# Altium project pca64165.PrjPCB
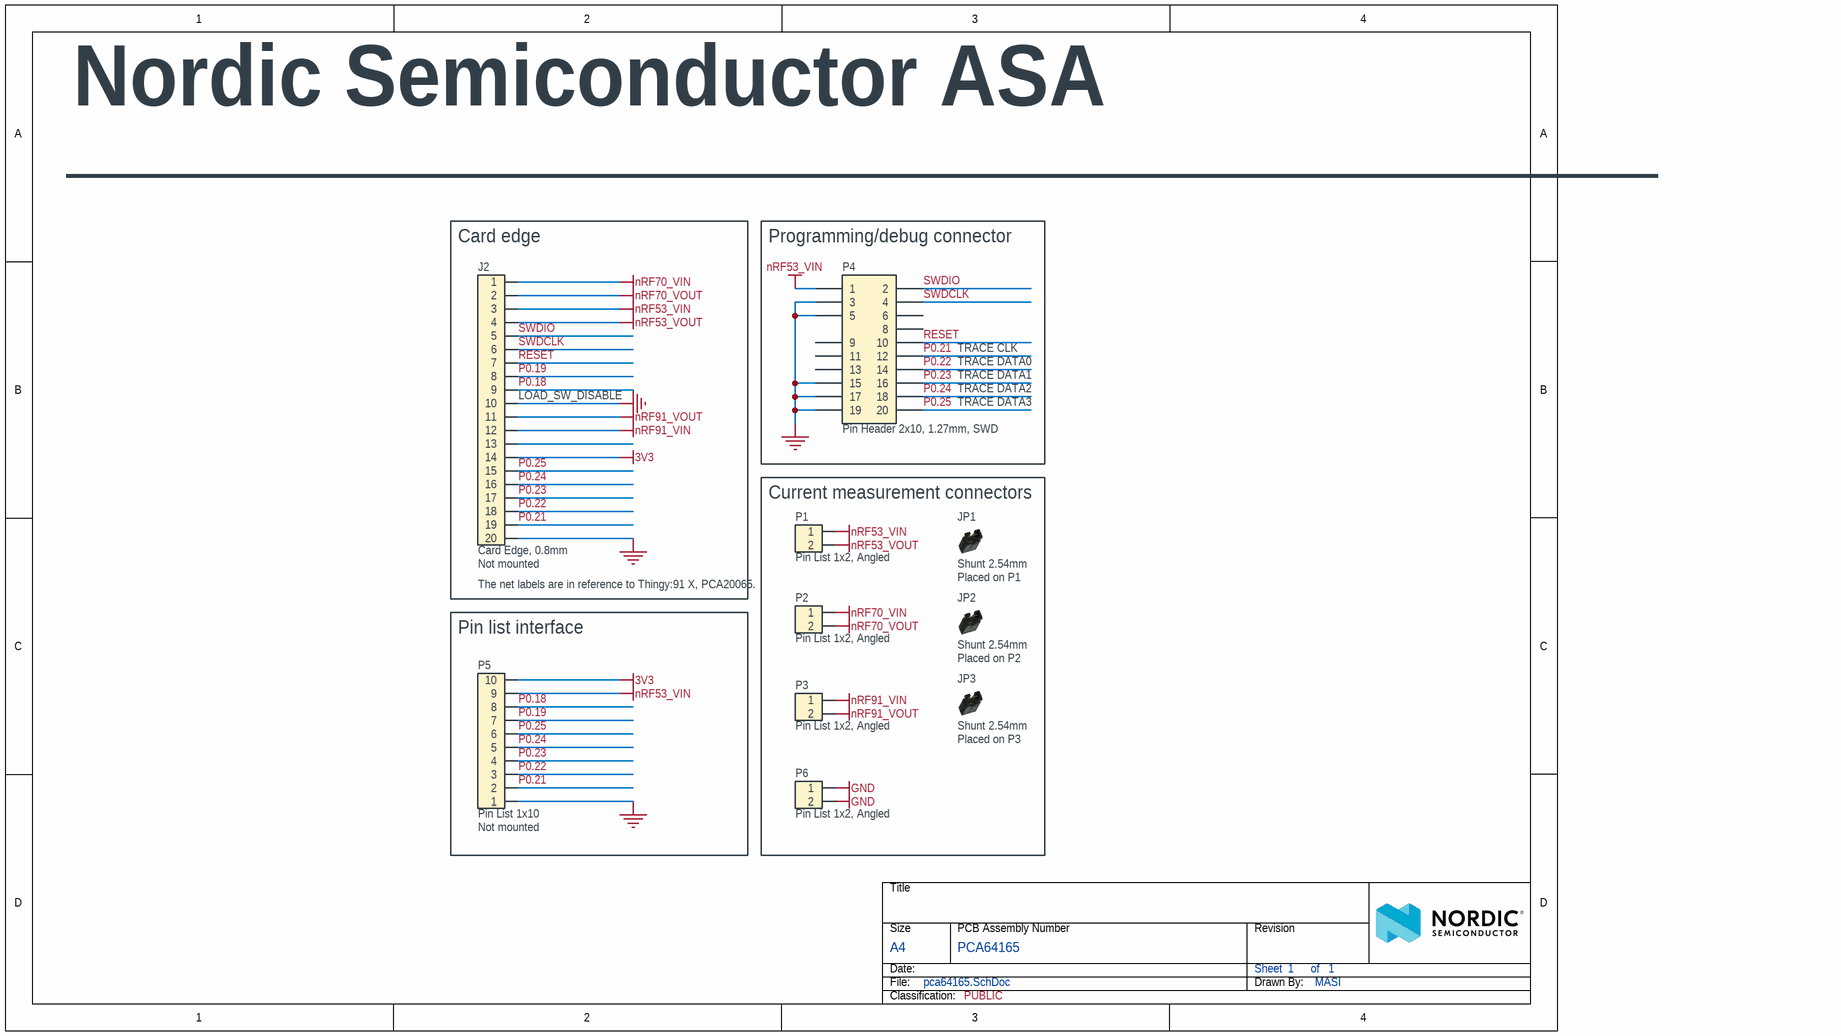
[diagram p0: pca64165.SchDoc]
Author: HANY/MASI; BoardThickness: 1.0mm; BoardTitle: Thingy:91 X Current Measurement and Debug Board; Classification: PUBLIC; Compliance: RoHS, REACH, Halogen-Free; Designer: HANY/MASI; Dielectric: FR-4 Halogen-Free IPC-4101/92; NrOfLayers: 2; Organization: Nordic Semiconductor; PCAName: PCA64165; PCARevision: 1.1.0; PCBNumber: 400763; PCBRevision: 0064HANY; PCBStackup: 2021.240176; ProductName: Thingy:91 X Current Measurement and Debug Board; ProjectName: Thingy:91 X; ProjectNumber: 4492; SilkscreenColor: White, Halogen Free; SoldermaskColor: Blue, Halogen Free; SurfaceFinish: ENIG Gold
1 sheet, 10 parts. Net scope: global (net labels, ports and power ports of the same name join across sheets).
Board file: 400763.PcbDoc

## Sheet pca64165.SchDoc: =BoardTitle
size A4; Organization: Nordic Semiconductor; Revision: 1.1.0; SheetNumber: 1; SheetTotal: 1; Author: HANY/MASI; CompanyName: Nordic Semiconductor; DrawnBy: MASI

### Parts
J2  Card Edge, 0.8mm  Assembly: Not mounted  [10056847-101LF_Mating_Board_Thingy91_v2]  (no BOM)
JP1  Shunt 2.54mm  Assembly: Placed on P1  [Shunt_2.54mm_Horizontal]
JP2  Shunt 2.54mm  Assembly: Placed on P2  [Shunt_2.54mm_Horizontal]
JP3  Shunt 2.54mm  Assembly: Placed on P3  [Shunt_2.54mm_Horizontal]
P1  Pin List 1x2, Angled  [LIST_ANG_1x2-SMD-2.54MM]
P2  Pin List 1x2, Angled  [LIST_ANG_1x2-SMD-2.54MM]
P3  Pin List 1x2, Angled  [LIST_ANG_1x2-SMD-2.54MM]
P4  Pin Header 2x10, 1.27mm, SWD  [HDR_2x10-SMD-1.27mm-K-SWD]
P5  Pin List 1x10  Assembly: Not mounted  [LIST_1x10-NC]
P6  Pin List 1x2, Angled  [LIST_ANG_1x2-SMD-2.54MM]

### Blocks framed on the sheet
Card edge: J2
Programming/debug connector: P4
Current measurement connectors: JP1-JP3 P1-P3 P6
Pin list interface: P5

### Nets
3V3: J2.14 P5.10
GND: J2.10 J2.20 P4.3 P4.5 P4.15 P4.17 P4.19 P5.1 P6.1 P6.2
nRF53_VIN: J2.3 P1.1 P4.1 P5.9
nRF53_VOUT: J2.4 P1.2
nRF70_VIN: J2.1 P2.1
nRF70_VOUT: J2.2 P2.2
nRF91_VIN: J2.12 P3.1
nRF91_VOUT: J2.11 P3.2
P0.18: J2.9 P5.8
P0.19: J2.8 P5.7
P0.21: J2.19 P4.12 P5.2
P0.22: J2.18 P4.14 P5.3
P0.23: J2.17 P4.16 P5.4
P0.24: J2.16 P4.18 P5.5
P0.25: J2.15 P4.20 P5.6
RESET: J2.7 P4.10
SWDCLK: J2.6 P4.4
SWDIO: J2.5 P4.2

Not connected (* = marked no-connect by the designer): J2 13; P4 6 8 9 11 13

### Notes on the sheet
- ____________________________________________________
- Nordic Semiconductor ASA
- TRACE CLK
- TRACE DATA0
- TRACE DATA1
- (near J2) LOAD_SW_DISABLE
- TRACE DATA2
- TRACE DATA3
- The net labels are in reference to Thingy:91 X, PCA20065.

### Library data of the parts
J2 = 10056847-101LF_Mating_Board_for_Thingy:91_v2: 0.8mm pitch, dual edge, right angle, SMD, card edge connector; Manufacturer: FCI; Part number NEMS: 100500798; Component Status: Active; Pad Count: 20; Note: N.A.
JP1-JP3 = SHUNT JUMPER 2.54mm Black Tin: Shunt Jumper 2.54mm Black, open top; Manufacturer: WCON; Manufacturer Part Number: 3710-6001OS0B05; Part number NEMS: 100500728; Pad Count: 2; Note: N.A.; Component Status: Active; System: Connector
P1-P3 P6 = Pin List Ang 1x2 SMD, 2.54mm: Pin List 1x2, 2.54mm (100mil), Right Angled, SMD; Manufacturer: WCON; Manufacturer Part Number: 1125B-1102S0Z135CR06; Part number NEMS: 100500354; Note: (Replaced 1125B-1102S0Z135R2); Artikkelnr Noca: N.A.; Pad Count: 2; Component Status: Active; System: Connector
P4 = Pin Header 2x10 SMD, 1.27mm, KS, SWD (Cabcon): Pin Header 2x10, 1.27mm (50mil), SMD, Keying Shroud, Removed Pin 7; Manufacturer: WCON; Manufacturer Part Number: 3132-20MS0BK00R5; Part number NEMS: 100500841,100500280; Note: (Replaced 3132-20MS0BK00R3); Artikkelnr Noca: N.A.; Pad Count: 19; Component Status: Active; System: Connector
P5 = Pin List 1x10, N.C.: Pin List 1x10, 2.54mm (100mil); Manufacturer: N.A.; Part number NEMS: 100500336; Pad Count: 10; Component Status: Active; System: Connector

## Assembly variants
Default: not fitted J2 P5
